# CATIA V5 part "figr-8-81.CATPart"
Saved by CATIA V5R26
Part number: Part1
Bounding box of the stored display mesh (mm): x -52.625 to 52.625, y -77.625 to 77.625, z 0 to 30
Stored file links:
  D:\_Deepak\CATIA\CATIA V5-6R2016_Deepak\Resources\Part files\Partfiles\c08_catia_v5_6r2016_prt\figr-8-81.CATPart
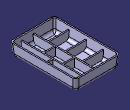
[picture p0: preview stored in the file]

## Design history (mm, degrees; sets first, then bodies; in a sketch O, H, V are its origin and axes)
Set1
  Plane1: type Offset, RefPlane xy-plane, Offset 30
  Plane2: type Offset, RefPlane face of Pad1, Offset -8, reversed
Body1 (main body)
  Sketch1 on xy-plane, origin (0, 0, 0), H (1, 0, 0), V (0, 1, 0)
    line L1 (-50, 75) -> (50, 75)
    line L2 (50, 75) -> (50, -75)
    line L3 (50, -75) -> (-50, -75)
    line L4 (-50, -75) -> (-50, 75)
    axis line L5 (50, -75) -> (-50, 75)
    length L3 = 100
    length L2 = 150
    horizontal: L1 H, L3 H
    vertical: L2 V, L4 V
    midpoint: O L5
  Pad1: profile Sketch1, direction (0, 0, 1), length 0, opposite side up to Plane1
  Draft1: Angle -5, Neutral face of Pad1, PullDir face of Pad1, SupportToDraft (face of Pad1; face of Pad1; face of Pad1; face of Pad1)
  Fillet1: radius 7, on edge [face of Pad1 | face of Pad1] (x4)
  Fillet2: radius 10, on edge [face of Pad1 | face of Pad1] (x4)
  Shell1: ExtOffset 0, Face face of Pad1, IntOffset 3
  Sketch2 on Plane2, origin (0, 0, 22), H (1, 0, 0), V (0, -1, 0)
    line L1 (28.1747, 54.0191) -> (28.1747, -59.2866)
    line L2 (0, 54.0191) -> (0, -59.2866)
    point P3 (0, 54.0191)
    line L3 (-9.5939, 0) -> (-33.0562, 0)
    point P5 (-9.5939, 0)
    line L4 (-9.5939, -40.4023) -> (-33.0562, -40.4023)
    point P7 (-9.5939, -40.4023)
    point P8 (-33.0562, -40.4023)
    point P9 (-33.0562, 40.4023)
    point P10 (-9.5939, 40.4023)
    line L5 (-9.5939, 40.4023) -> (-33.0562, 40.4023)
    line L6 (28.1747, 22.6983) -> (0, 22.6983)
    point P11 (28.1747, 22.6983)
    point P12 (0, 22.6983)
    point P13 (0, -22.6983)
    point P14 (28.1747, -22.6983)
    line L7 (28.1747, -22.6983) -> (0, -22.6983)
    line L8 (28.1747, 0) -> (41.8849, 0)
    point P15 (28.1747, 0)
    vertical: L1 V, L2 V
    coincidence: P3 V, P5 H, P11 L1, P12 L2, P15 L1, P15 H
    horizontal: L3 H, L4 H, L6 H, L8 H
    symmetry: P8 P9 L3, P7 P10 L3, L4 L5 L3, P12 P13 H, P11 P14 H, L6 L7 H
  Stiffener1: ExtendedProfile Sketch2, ThicknessTop 1, ThicknessValue 3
